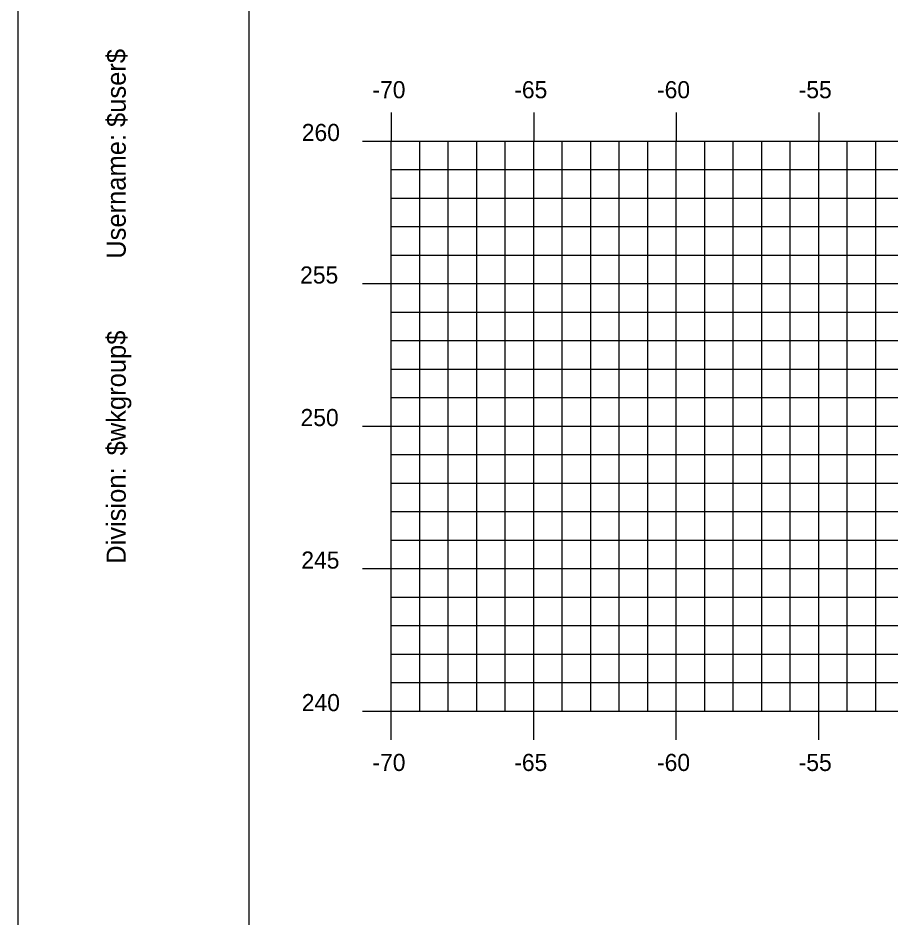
# Model space of a CAD drawing. Extents: x 859352 to 859522, y 366268 to 366378.
# Drawn here: x 859352.04 to 859382.63, y 366299.98 to 366331.55 of the extents above; entities that cross this region are included whole.
import ezdxf

# ---------------------------------------------------------------- set-up
doc = ezdxf.new("R2010")
doc.units = 0
for name, color, linetype in [('BORDER', 7, 'Continuous'), ('H_V ANNOTATION', 7, 'Continuous'), ('MAJOR', 7, 'Continuous'), ('MINOR', 7, 'Continuous'), ('PLOT BOUNDARY', 7, 'Continuous')]:
    doc.layers.add(name, color=color, linetype=linetype)

msp = doc.modelspace()

# ---------------------------------------------------------------- linework, layer by layer
at = {"layer": 'BORDER'}
msp.add_line((859360.13, 366376.236), (859360.13, 366271.236), dxfattribs=at)
at = {"layer": 'MAJOR'}
for p, q in [((859365.129, 366328.238), (859365.129, 366327.236)), ((859370.129, 366328.238), (859370.129, 366327.236)), ((859375.129, 366328.238), (859375.129, 366327.236)), ((859380.129, 366328.238), (859380.129, 366327.236)), ((859364.127, 366327.236), (859365.129, 366327.236)), ((859365.129, 366327.236), (859505.129, 366327.236)), ((859365.129, 366307.236), (859365.129, 366327.236)), ((859365.129, 366307.236), (859365.129, 366327.236)), ((859365.129, 366327.236), (859505.129, 366327.236)), ((859370.129, 366307.236), (859370.129, 366327.236)), ((859375.129, 366307.236), (859375.129, 366327.236)), ((859380.129, 366307.236), (859380.129, 366327.236)), ((859364.127, 366322.236), (859365.129, 366322.236)), ((859365.129, 366322.236), (859505.129, 366322.236)), ((859364.127, 366317.236), (859365.129, 366317.236)), ((859365.129, 366317.236), (859505.129, 366317.236)), ((859364.127, 366312.236), (859365.129, 366312.236)), ((859365.129, 366312.236), (859505.129, 366312.236)), ((859364.127, 366307.236), (859365.129, 366307.236)), ((859365.129, 366307.236), (859505.129, 366307.236)), ((859365.129, 366307.236), (859505.129, 366307.236)), ((859365.129, 366306.234), (859365.129, 366307.236)), ((859370.129, 366306.234), (859370.129, 366307.236)), ((859375.129, 366306.234), (859375.129, 366307.236)), ((859380.129, 366306.234), (859380.129, 366307.236))]:
    msp.add_line(p, q, dxfattribs=at)
at = {"layer": 'MINOR'}
for p, q in [((859365.129, 366307.236), (859365.129, 366327.236)), ((859366.129, 366307.236), (859366.129, 366327.236)), ((859367.129, 366307.236), (859367.129, 366327.236)), ((859368.129, 366307.236), (859368.129, 366327.236)), ((859369.129, 366307.236), (859369.129, 366327.236)), ((859371.129, 366307.236), (859371.129, 366327.236)), ((859372.129, 366307.236), (859372.129, 366327.236)), ((859373.129, 366307.236), (859373.129, 366327.236)), ((859374.129, 366307.236), (859374.129, 366327.236)), ((859376.129, 366307.236), (859376.129, 366327.236)), ((859377.129, 366307.236), (859377.129, 366327.236)), ((859378.129, 366307.236), (859378.129, 366327.236)), ((859379.129, 366307.236), (859379.129, 366327.236)), ((859381.129, 366307.236), (859381.129, 366327.236)), ((859382.129, 366307.236), (859382.129, 366327.236)), ((859365.129, 366326.236), (859505.129, 366326.236)), ((859365.129, 366326.236), (859366.131, 366326.236)), ((859365.129, 366325.236), (859505.129, 366325.236)), ((859365.129, 366325.236), (859366.131, 366325.236)), ((859365.129, 366324.236), (859505.129, 366324.236)), ((859365.129, 366324.236), (859366.131, 366324.236)), ((859365.129, 366323.236), (859505.129, 366323.236)), ((859365.129, 366323.236), (859366.131, 366323.236)), ((859365.129, 366321.236), (859505.129, 366321.236)), ((859365.129, 366321.236), (859366.131, 366321.236)), ((859365.129, 366320.236), (859505.129, 366320.236)), ((859365.129, 366320.236), (859366.131, 366320.236)), ((859365.129, 366319.236), (859505.129, 366319.236)), ((859365.129, 366319.236), (859366.131, 366319.236)), ((859365.129, 366318.236), (859505.129, 366318.236)), ((859365.129, 366318.236), (859366.131, 366318.236)), ((859365.129, 366316.236), (859505.129, 366316.236)), ((859365.129, 366316.236), (859366.131, 366316.236)), ((859365.129, 366315.236), (859505.129, 366315.236)), ((859365.129, 366315.236), (859366.131, 366315.236)), ((859365.129, 366314.236), (859505.129, 366314.236)), ((859365.129, 366314.236), (859366.131, 366314.236)), ((859365.129, 366313.236), (859505.129, 366313.236)), ((859365.129, 366313.236), (859366.131, 366313.236)), ((859365.129, 366311.236), (859505.129, 366311.236)), ((859365.129, 366311.236), (859366.131, 366311.236)), ((859365.129, 366310.236), (859505.129, 366310.236)), ((859365.129, 366310.236), (859366.131, 366310.236)), ((859365.129, 366309.236), (859505.129, 366309.236)), ((859365.129, 366309.236), (859366.131, 366309.236)), ((859365.129, 366308.236), (859505.129, 366308.236)), ((859365.129, 366308.236), (859366.131, 366308.236))]:
    msp.add_line(p, q, dxfattribs=at)
at = {"layer": 'PLOT BOUNDARY'}
msp.add_lwpolyline([(859352.036, 366268.177), (859522.036, 366268.177), (859522.036, 366378.177), (859352.036, 366378.177)], close=True, dxfattribs=at)

# ---------------------------------------------------------------- texts
at = {"layer": 'BORDER'}
for s, p in [('$user$', (859355.815, 366327.728)), ('Username:', (859355.815, 366323.104)), ('$wkgroup$', (859355.815, 366316.206)), ('Division:', (859355.815, 366312.403))]:
    msp.add_text(s, height=0.6696, rotation=90, dxfattribs=at).set_placement(p)
at = {"layer": 'H_V ANNOTATION'}
for s, p in [('-70', (859364.471, 366328.736)), ('-65', (859369.447, 366328.736)), ('-60', (859374.455, 366328.736)), ('-55', (859379.426, 366328.736)), ('260', (859361.992, 366327.236)), ('255', (859361.933, 366322.236)), ('250', (859361.949, 366317.236)), ('245', (859361.976, 366312.236)), ('240', (859361.992, 366307.236)), ('-70', (859364.471, 366305.136)), ('-65', (859369.447, 366305.136)), ('-60', (859374.455, 366305.136)), ('-55', (859379.426, 366305.136))]:
    msp.add_text(s, height=0.6, dxfattribs=at).set_placement(p)

doc.saveas('drawing.dxf')
